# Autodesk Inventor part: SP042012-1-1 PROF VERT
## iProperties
Created: 2013-01
Part Number: SP042012-1-1 PROF VERT
Material: Aluminum-6061
Description: PROFILE 45X45 UL
Document SubType Name: Modeling
Designer: Administrator
Stock Number: 20.1063 PROFILE 45X45 UL
Density: 2.71 g/cm^3
Mass: 1462.47 g
Surface Area: 6404.2 cm^2
Volume: 539.657 cm^3
FINISH: CLEAR ANODIZED
Author: Administrator
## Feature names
1. Extrusion1
